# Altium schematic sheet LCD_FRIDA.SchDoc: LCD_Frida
size A3; Author: N.P; CompanyName: STMicroelectronics; Organization: MCD/APPLICATIONS/LMS; DocumentNumber: MB1260; SheetNumber: 10; SheetTotal: 13; Project: STM32F723e-DISCO; PageSetup: Record=PageOptions¦CenterHorizontal=True¦CenterVertical=True¦PrintScale=1.00¦XCorrection=1.00¦YCorrection=1.00¦PrintKind=1¦BorderSize=5000000¦LeftOffset=0¦BottomOffset=0¦Orientation=2¦PaperLength=1000¦PaperWidth=1000¦Scale=100¦PaperSource=7¦PrintQuality=-3¦MediaType=1¦DitherType=10¦PrintScaleMode=1¦PaperKind=Letter¦PaperIndex=1
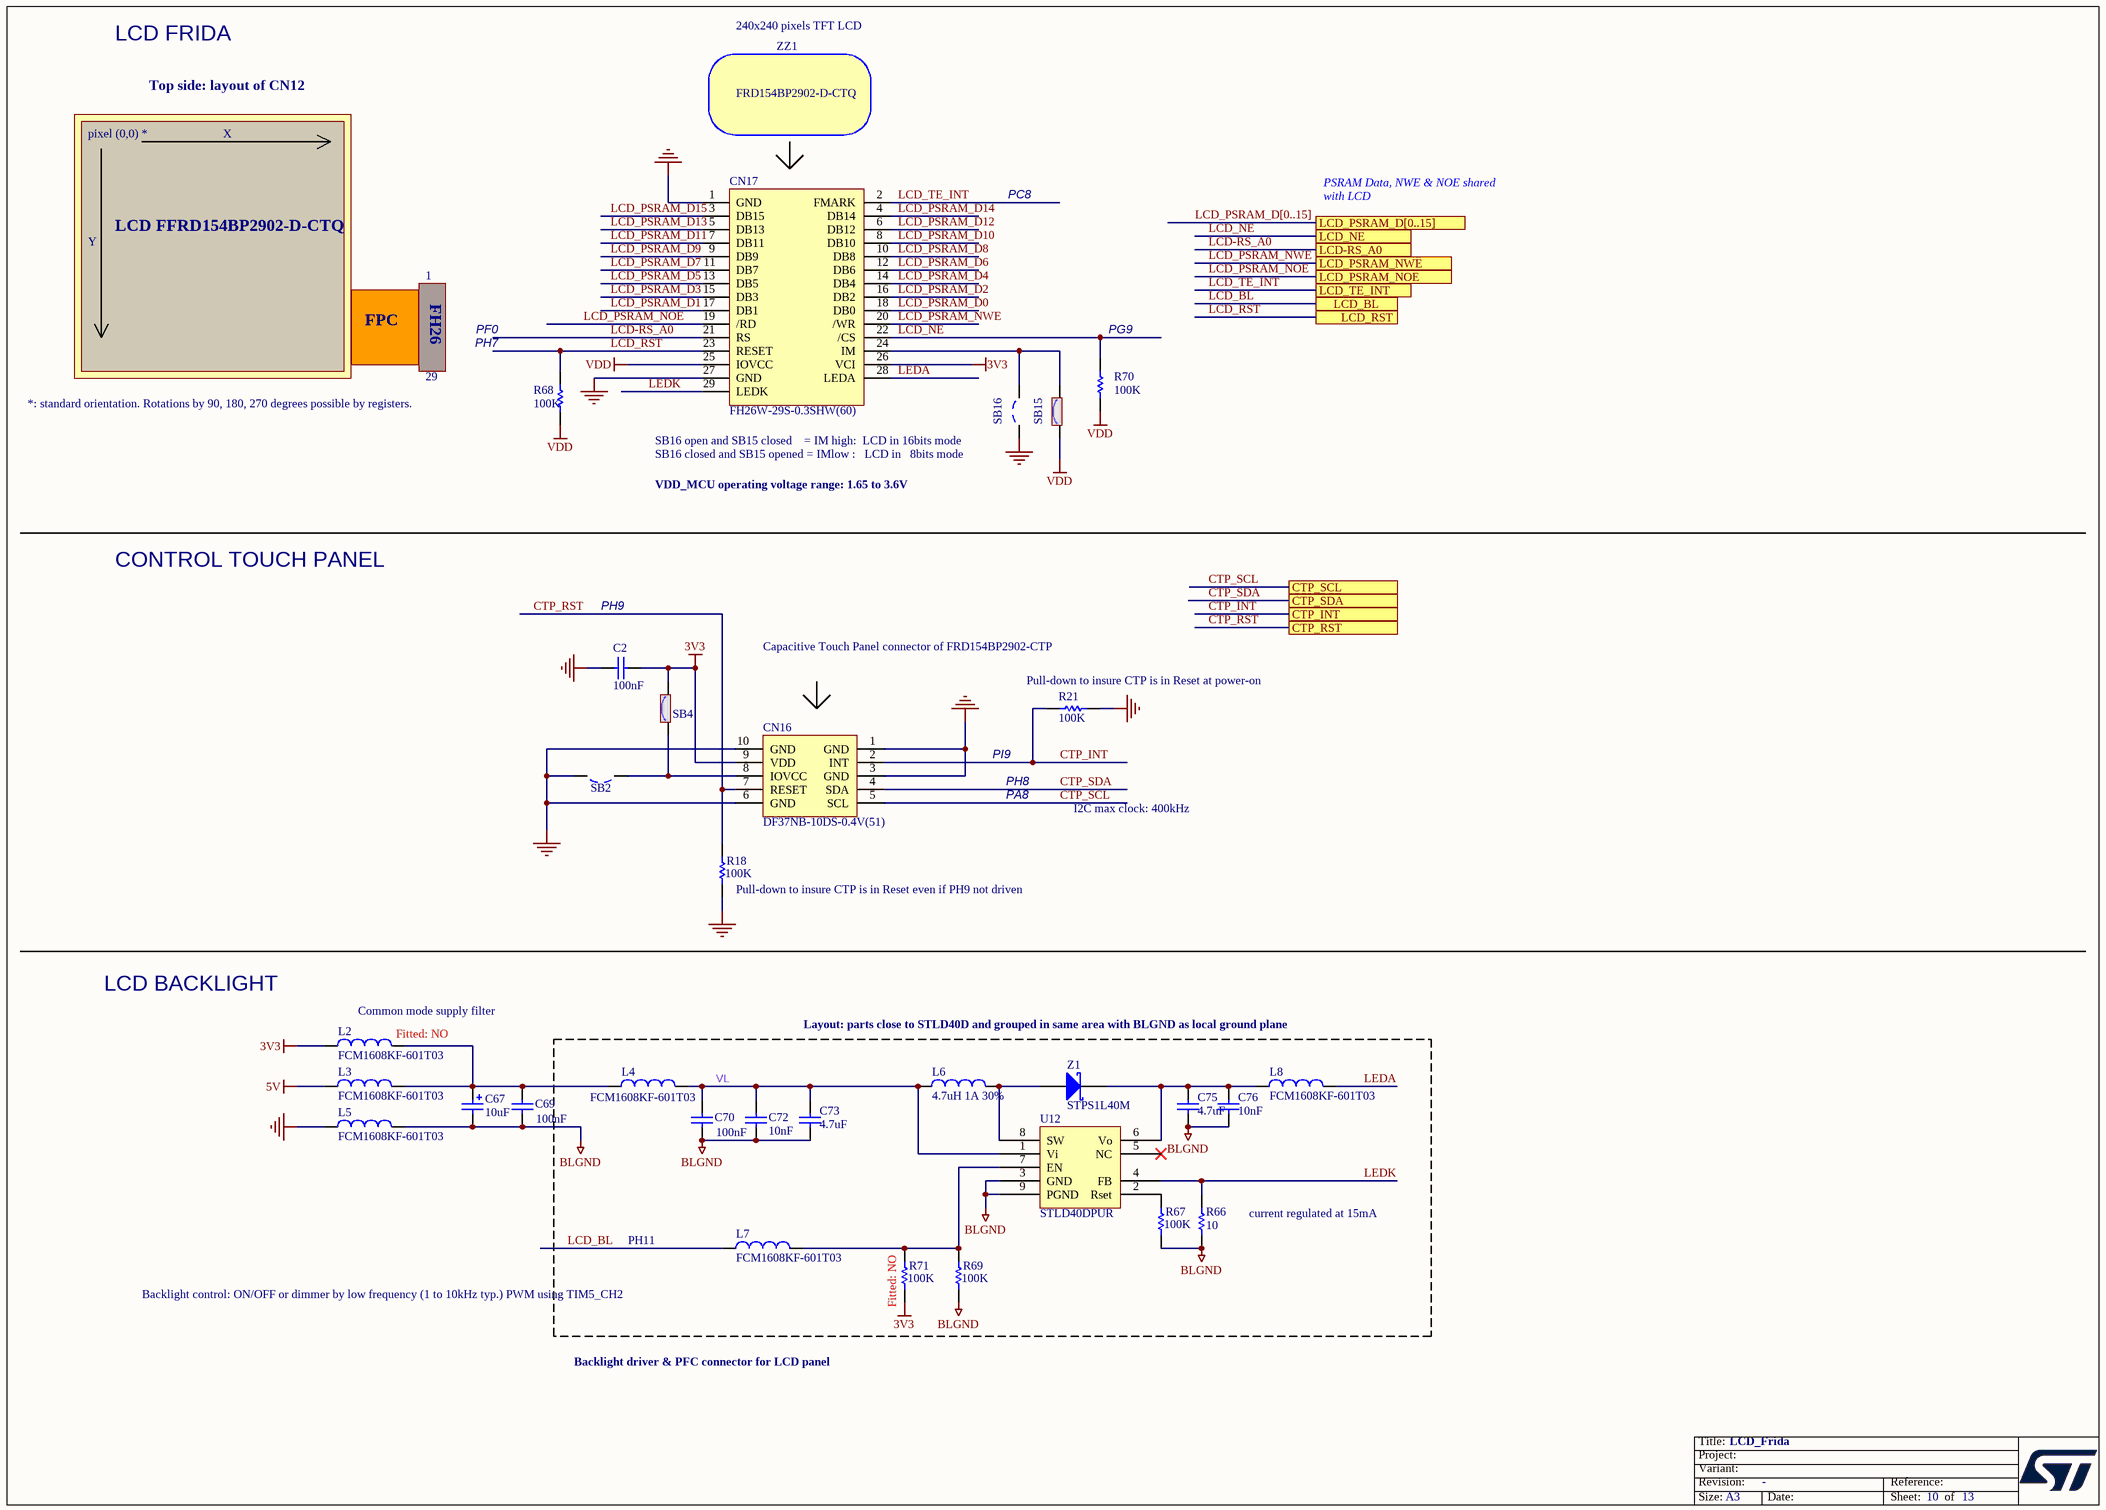
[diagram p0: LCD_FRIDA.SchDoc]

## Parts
C2  100nF  [0402C]
C67  value 10uF  [TAN-A]  (hidden comment: 10uF_POL_10%_TANA)
C69  100nF  [0402C]
C70  100nF  [0402C]
C72  value 10nF  [0603C]  (hidden comment: 10nF_X7R_10%_0603)
C73  value 4.7uF  [1206C]  (hidden comment: 4.7uF_X7R_10%_1206)
C75  value 4.7uF  [1206C]  (hidden comment: 4.7uF_X7R_10%_1206)
C76  value 10nF  [0603C]  (hidden comment: 10nF_X7R_10%_0603)
CN16  DF37NB-10DS-0.4V(51)  [DF37NB-10DS-0R4V]
CN17  FH26W-29S-0.3SHW(60)  [FH26-29S-0R3SHW]
L2  FCM1608KF-601T03  Fitted: NO  [0603L]
L3  FCM1608KF-601T03  [0603L]
L4  FCM1608KF-601T03  [0603L]
L5  FCM1608KF-601T03  [0603L]
L6  4.7uH 1A 30%  [1210L]
L7  FCM1608KF-601T03  [0603L]
L8  FCM1608KF-601T03  [0603L]
R18  value 100K  [0402R]  (hidden comment: 100K_1%_0402)
R21  value 100K  [0402R]  (hidden comment: 100K_1%_0402)
R66  value 10  [0603R]  (hidden comment: 10_1%_0603)
R67  value 100K  [0402R]  (hidden comment: 100K_1%_0402)
R68  value 100K  [0402R]  (hidden comment: 100K_1%_0402)
R69  value 100K  [0402R]  (hidden comment: 100K_1%_0402)
R70  value 100K  [0402R]  (hidden comment: 100K_1%_0402)
R71  value 100K  Fitted: NO  [0402R]  (hidden comment: 100K_1%_0402)
SB2  Solder Bridge OFF  [JP2_SMD]  (value not drawn)
SB4  Solder Bridge ON  [JP2_SMD]  (value not drawn)
SB15  Solder Bridge ON  [JP2_SMD]  (value not drawn)
SB16  Solder Bridge OFF  [JP2_SMD]  (value not drawn)
U12  STLD40DPUR  [SON8_0R65_3X3]
Z1  STPS1L40M  [DO-216AA]
ZZ1  FRD154BP2902-D-CTQ

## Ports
CTP_INT, CTP_RST, CTP_SCL, CTP_SDA, LCD-RS_A0, LCD_BL, LCD_NE, LCD_PSRAM_D[0..15], LCD_PSRAM_NOE, LCD_PSRAM_NWE, LCD_RST, LCD_TE_INT

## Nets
3V3: C2.1 CN16.9(VDD) CN17.26(VCI) L2.1 R71.1 SB4.2
5V: L3.1
BLGND: C67.2 C69.1 C70.1 C72.1 C73.1 C75.1 C76.1 L5.2 R66.1 R67.1 R69.1 U12.3(GND) U12.9(PGND)
GND: C2.2 CN16.1(GND) CN16.3(GND) CN16.6(GND) CN16.10(GND) CN17.1(GND) CN17.27(GND) L5.1 R18.1 R21.1 SB2.2 SB16.1
VDD: CN17.25(IOVCC) R68.1 R70.1 SB15.1
CTP_INT: CN16.2(INT) R21.2 ; port CTP_INT
CTP_RST: CN16.7(RESET) R18.2 ; port CTP_RST
CTP_SCL: CN16.5(SCL) ; port CTP_SCL
CTP_SDA: CN16.4(SDA) ; port CTP_SDA
LCD-RS_A0: CN17.21(RS) ; port LCD-RS_A0
LCD_BL: L7.1 ; port LCD_BL
LCD_NE: CN17.22(/CS) R70.2 ; port LCD_NE
LCD_PSRAM_D0: CN17.18(DB0)
LCD_PSRAM_D1: CN17.17(DB1)
LCD_PSRAM_D2: CN17.16(DB2)
LCD_PSRAM_D3: CN17.15(DB3)
LCD_PSRAM_D4: CN17.14(DB4)
LCD_PSRAM_D5: CN17.13(DB5)
LCD_PSRAM_D6: CN17.12(DB6)
LCD_PSRAM_D7: CN17.11(DB7)
LCD_PSRAM_D8: CN17.10(DB8)
LCD_PSRAM_D9: CN17.9(DB9)
LCD_PSRAM_D10: CN17.8(DB10)
LCD_PSRAM_D11: CN17.7(DB11)
LCD_PSRAM_D12: CN17.6(DB12)
LCD_PSRAM_D13: CN17.5(DB13)
LCD_PSRAM_D14: CN17.4(DB14)
LCD_PSRAM_D15: CN17.3(DB15)
LCD_PSRAM_NOE: CN17.19(/RD) ; port LCD_PSRAM_NOE
LCD_PSRAM_NWE: CN17.20(/WR) ; port LCD_PSRAM_NWE
LCD_RST: CN17.23(RESET) R68.2 ; port LCD_RST
LCD_TE_INT: CN17.2(FMARK) ; port LCD_TE_INT
LEDA: CN17.28(LEDA) L8.2
LEDK: CN17.29(LEDK) R66.2 U12.4(FB)
VL: C70.2 C72.2 C73.2 L4.2 L6.1 U12.1(Vi)
NetC67_1: C67.1 C69.2 L2.2 L3.2 L4.1
NetC75_2: C75.2 C76.2 L8.1 U12.6(Vo) Z1.2(K)
NetCN16_8: CN16.8(IOVCC) SB2.1 SB4.1
NetCN17_24: CN17.24(IM) SB15.2 SB16.2
NetL6_2: L6.2 U12.8(SW) Z1.1(A)
NetL7_2: L7.2 R69.2 R71.2 U12.7(EN)
NetR67_2: R67.2 U12.2(Rset)

Not connected (* = marked no-connect by the designer): U12 5(NC)*

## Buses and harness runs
bus LCD_PSRAM_D[0..15] = port LCD_PSRAM_D[0..15]

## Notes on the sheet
- LCD FRIDA
- 240x240 pixels TFT LCD
- Top side: layout of CN12
- pixel (0,0) *
- X
- Y
- LCD FFRD154BP2902-D-CTQ
- PC8
- PSRAM Data, NWE & NOE shared with LCD
- 1
- FH26
- FPC
- 29
- PF0
- PH7
- (near R70) PG9
- (near R68) *: standard orientation. Rotations by 90, 180, 270 degrees possible by registers.
- SB16 open and SB15 closed    = IM high:  LCD in 16bits mode
  SB16 closed and SB15 opened = IMlow :   LCD in   8bits mode
- VDD_MCU operating voltage range: 1.65 to 3.6V
- CONTROL TOUCH PANEL
- PH9
- Capacitive Touch Panel connector of FRD154BP2902-CTP
- (near R21) Pull-down to insure CTP is in Reset at power-on
- PI9
- PH8
- PA8
- I2C max clock: 400kHz
- (near R18) Pull-down to insure CTP is in Reset even if PH9 not driven
- LCD BACKLIGHT
- (near L2) Common mode supply filter
- Layout: parts close to STLD40D and grouped in same area with BLGND as local ground plane
- PH11
- (near R66) current regulated at 15mA
- Backlight control: ON/OFF or dimmer by low frequency (1 to 10kHz typ.) PWM using TIM5_CH2
- Backlight driver & PFC connector for LCD panel

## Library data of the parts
C2 C69 C70 = Cap_100nF_X7R_10%_0402: Capacitor,100nF,16V,X7R,10%,0402,YAGEO; Manuf_Part_1: CC0402KRX7R7BB104; Ordered by: Subcon; Fitted: YES
C67 = Cap_10uF_POL_10%_TANA: Polarized Capacitor,10uF,10V,10%,typeA,VISHAY; Manuf_Part_1: 293D106X9010A2TE3; Ordered by: Subcon; Fitted: YES
C72 C76 = Cap_10nF_X7R_10%_0603: Capacitor,10nF,50V,X7R,10%,0603,YAGEO; Manuf_Part_1: CC0603KRX7R9BB103; Ordered by: Subcon; Fitted: YES
C73 C75 = Cap_4.7uF_X7R_10%_1206: Capacitor,4.7uF,50V, X7R,10%,1206,AVX; Manuf_Part_1: 12065C475KAT2A; Ordered by: Subcon; Fitted: YES
CN16 = Header 5X2A: Header, 5-Pin, Dual row; Manuf_1: Hirose; Ordered by: Subcon; Fitted: YES
CN17 = FH26-29S-0.3SHW: 29pins FPC connector; Manuf_1: Hirose; Ordered by: Subcon; Fitted: YES
L2 = BEAD_600R_350MA_0603: Bead,600R,350mA,0603,FCM1608KF-601T03,Tai-tech; Manuf_2: TDK; Manuf_Part_2: MPZ1608S300A; Manuf_Part_3: BLM18PG121SN1D; Manuf_3: MURATA; Value: 100uH; Description_2: Bead,30R,5A,0603,MPZ1608S300A,TDK; Description_3: Bead,120R,2A,0603,BLM18PG121SN1D,MURATA; Fitted: NO; Ordered by: Subcon
L3-L5 L7 L8 = BEAD_600R_350MA_0603: Bead,600R,350mA,0603,FCM1608KF-601T03,Tai-tech; Manuf_2: TDK; Manuf_Part_2: MPZ1608S300A; Manuf_Part_3: BLM18PG121SN1D; Manuf_3: MURATA; Value: 100uH; Description_2: Bead,30R,5A,0603,MPZ1608S300A,TDK; Description_3: Bead,120R,2A,0603,BLM18PG121SN1D,MURATA; Ordered by: Subcon; Fitted: YES
L6 = Ind_4.7uH_1A_30%: FIXED IND 4.7UH 1A 180 MOHM 30% SMD; Manuf_Part_1: LQH32PN4R7NN0L; Manuf_1: MURATA; Order: 490-5338-1-ND; Ordered by: Subcon; Fitted: YES
R18 R21 R67-R70 = Res_100K_1%_0402: Resistor,100K,0402,1%,YAGEO; Manuf_Part_2: RT0402FRE07100KL; Manuf_Part_1: RC0402FR-07100KL; Ordered by: Subcon; Fitted: YES
R66 = Res_10_1%_0603: Resistor,10,0603,1%,ROHM,1/4W; Manuf_Part_1: ESR03EZPF10R0; Ordered by: Subcon; Fitted: YES
R71 = Res_100K_1%_0402: Resistor,100K,0402,1%,YAGEO; Manuf_Part_2: RT0402FRE07100KL; Manuf_Part_1: RC0402FR-07100KL; Ordered by: Subcon
SB2 SB16 = SB_OFF: Fitted: NO; Ordered by: Subcon
SB4 SB15 = SB_ON: Fitted: YES; Ordered by: Subcon
U12 = STLD40DPMR: White LED power supply for large display backlight; Manuf_1: STM; Ordered by: ST; Ref St: 9176009; ECCN_US/EU: EAR99/NEC; Fitted: YES
Z1 = D Schottky: Schottky Diode; Manuf_1: STM; Code - JEDEC: DO-214-AA; Ordered by: ST; Ref St: 9151085; ECCN_US/EU: EAR99/NEC; Fitted: YES
ZZ1 = BoM_Item: Frida LCD + Capacitive Touch Panel; Manuf_Part_1: FRD154BP2902-CTP; Ordered by: Subcon; ECCN_US/EU: EAR99/NEC; Fitted: YES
